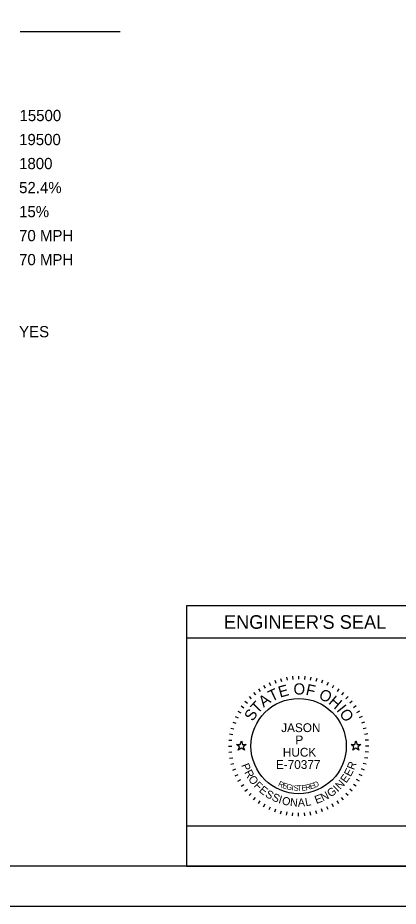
# Model space of a CAD drawing. Extents: x 39.8 to 73.8, y 13 to 35.
# Drawn here: x 47.48 to 52.23, y 12.96 to 24.06 of the extents above; entities that cross this region are included whole.
import ezdxf

# ---------------------------------------------------------------- set-up
doc = ezdxf.new("R2010")
doc.units = 0
for name, color, linetype in [('Default', 7, 'Continuous'), ('SH_Border', 7, 'Continuous'), ('SH_Cut_Line', 7, 'Continuous'), ('SH_Data', 7, 'Continuous'), ('SH_Text', 7, 'Continuous')]:
    doc.layers.add(name, color=color, linetype=linetype)

msp = doc.modelspace()

# ---------------------------------------------------------------- linework, layer by layer
at = {"layer": 'Default'}
for points in [[(50.214, 14.985), (50.26, 14.985), (50.275, 15.03), (50.289, 14.985), (50.336, 14.985), (50.298, 14.957), (50.313, 14.913), (50.275, 14.94), (50.237, 14.913), (50.251, 14.957)], [(51.644, 14.985), (51.69, 14.985), (51.705, 15.03), (51.719, 14.985), (51.766, 14.985), (51.728, 14.957), (51.743, 14.913), (51.705, 14.94), (51.667, 14.913), (51.681, 14.957)]]:
    msp.add_lwpolyline(points, close=True, dxfattribs=at)
at = {"layer": 'SH_Border'}
msp.add_lwpolyline([(41.263, 34.465), (73.263, 34.465), (73.263, 13.465), (41.263, 13.465)], close=True, dxfattribs=at)
at = {"layer": 'SH_Cut_Line'}
msp.add_lwpolyline([(39.763, 12.965), (73.763, 12.965), (73.763, 34.965), (39.763, 34.965)], close=True, dxfattribs=at)
at = {"layer": 'SH_Data'}
for p, q in [((48.763, 23.887), (47.513, 23.887)), ((52.39, 16.715), (49.59, 16.715)), ((49.59, 16.715), (49.59, 13.465)), ((52.39, 16.315), (49.59, 16.315)), ((50.62, 15.758), (50.637, 15.722)), ((50.691, 15.787), (50.704, 15.75)), ((50.763, 15.81), (50.774, 15.772)), ((50.838, 15.827), (50.845, 15.787)), ((50.914, 15.837), (50.917, 15.797)), ((50.99, 15.84), (50.99, 15.8)), ((51.066, 15.837), (51.063, 15.797)), ((51.142, 15.827), (51.135, 15.787)), ((51.216, 15.81), (51.206, 15.772)), ((51.289, 15.787), (51.275, 15.75)), ((51.36, 15.758), (51.343, 15.722)), ((50.488, 15.682), (50.511, 15.649)), ((50.552, 15.723), (50.572, 15.688)), ((51.427, 15.723), (51.407, 15.688)), ((51.492, 15.682), (51.469, 15.649)), ((50.371, 15.584), (50.399, 15.555)), ((50.427, 15.635), (50.453, 15.605)), ((51.552, 15.635), (51.527, 15.605)), ((51.609, 15.584), (51.58, 15.555)), ((50.273, 15.467), (50.306, 15.444)), ((50.32, 15.527), (50.35, 15.502)), ((51.66, 15.527), (51.63, 15.502)), ((51.707, 15.467), (51.674, 15.444)), ((50.197, 15.335), (50.233, 15.318)), ((50.232, 15.402), (50.267, 15.382)), ((51.748, 15.402), (51.713, 15.382)), ((51.783, 15.335), (51.747, 15.318)), ((50.168, 15.264), (50.205, 15.251)), ((51.812, 15.264), (51.775, 15.251)), ((50.128, 15.117), (50.168, 15.11)), ((50.145, 15.191), (50.183, 15.181)), ((51.835, 15.191), (51.796, 15.181)), ((51.852, 15.117), (51.812, 15.11)), ((50.118, 15.041), (50.158, 15.038)), ((51.862, 15.041), (51.822, 15.038)), ((50.115, 14.965), (50.155, 14.965)), ((50.118, 14.889), (50.158, 14.892)), ((51.862, 14.889), (51.822, 14.892)), ((51.865, 14.965), (51.825, 14.965)), ((50.128, 14.813), (50.168, 14.82)), ((51.852, 14.813), (51.812, 14.82)), ((50.145, 14.739), (50.183, 14.749)), ((50.168, 14.666), (50.205, 14.679)), ((51.812, 14.666), (51.775, 14.679)), ((51.835, 14.739), (51.796, 14.749)), ((50.197, 14.595), (50.233, 14.612)), ((50.232, 14.527), (50.267, 14.547)), ((51.748, 14.527), (51.713, 14.547)), ((51.783, 14.595), (51.747, 14.612)), ((50.273, 14.463), (50.306, 14.486)), ((50.32, 14.403), (50.35, 14.428)), ((51.66, 14.403), (51.63, 14.428)), ((51.707, 14.463), (51.674, 14.486)), ((50.371, 14.346), (50.399, 14.375)), ((50.427, 14.295), (50.453, 14.325)), ((51.552, 14.295), (51.527, 14.325)), ((51.609, 14.346), (51.58, 14.375)), ((50.488, 14.248), (50.511, 14.281)), ((50.552, 14.207), (50.572, 14.242)), ((50.62, 14.172), (50.637, 14.208)), ((51.36, 14.172), (51.343, 14.208)), ((51.427, 14.207), (51.407, 14.242)), ((51.492, 14.248), (51.469, 14.281)), ((50.691, 14.143), (50.704, 14.18)), ((50.763, 14.12), (50.774, 14.158)), ((50.838, 14.103), (50.845, 14.143)), ((50.914, 14.093), (50.917, 14.133)), ((50.99, 14.09), (50.99, 14.13)), ((51.066, 14.093), (51.063, 14.133)), ((51.142, 14.103), (51.135, 14.143)), ((51.216, 14.12), (51.206, 14.158)), ((51.289, 14.143), (51.275, 14.18)), ((52.39, 13.465), (49.59, 13.465))]:
    msp.add_line(p, q, dxfattribs=at)
msp.add_lwpolyline([(52.39, 13.465), (52.39, 13.965), (49.59, 13.965), (49.59, 13.465)], close=True, dxfattribs=at)
msp.add_circle((50.99, 14.965), 0.595, dxfattribs=at)

# ---------------------------------------------------------------- texts
for s, height, p in [("ENGINEER'S SEAL", 0.17, (50.057, 16.43)), ('JASON', 0.11, (50.772, 15.14)), ('P', 0.11, (50.95, 14.987)), ('HUCK', 0.11, (50.793, 14.833)), ('E-70377', 0.11, (50.706, 14.68))]:
    msp.add_text(s, height=height, dxfattribs=at).set_placement(p)
for s, height, rotation, p in [('T', 0.14, 25.7167, (50.652, 15.517)), ('E', 0.14, 15.7571, (50.758, 15.569)), ('O', 0.14, 359.7812, (50.925, 15.609)), ('F', 0.14, 347.4362, (51.071, 15.607)), ('O', 0.14, 332.2586, (51.23, 15.566)), ('T', 0.14, 46.4344, (50.478, 15.361)), ('A', 0.14, 36.4747, (50.553, 15.443)), ('H', 0.14, 319.9136, (51.353, 15.501)), ('S', 0.14, 57.1924, (50.418, 15.266)), ('I', 0.14, 308.367, (51.456, 15.413)), ('O', 0.14, 303.1491, (51.492, 15.374)), ('R', 0.1, 69.2322, (51.682, 14.66)), ('P', 0.1, 291.494, (50.272, 14.727)), ('R', 0.1, 298.7311, (50.309, 14.637)), ('E', 0.1, 61.9951, (51.638, 14.575)), ('O', 0.1, 306.4666, (50.355, 14.553)), ('N', 0.1, 47.0224, (51.51, 14.416)), ('E', 0.1, 54.758, (51.583, 14.496)), ('F', 0.1, 314.7068, (50.424, 14.463)), ('E', 0.1, 321.4393, (50.488, 14.4)), ('R', 0.07, 334.487, (50.727, 14.47)), ('E', 0.07, 341.04, (50.781, 14.445)), ('G', 0.07, 347.4752, (50.831, 14.427)), ('I', 0.07, 353.7858, (50.899, 14.412)), ('S', 0.07, 356.8926, (50.926, 14.408)), ('T', 0.07, 3.0061, (50.976, 14.404)), ('E', 0.07, 6.0117, (51.029, 14.406)), ('R', 0.07, 11.9184, (51.082, 14.412)), ('E', 0.07, 17.6836, (51.14, 14.425)), ('D', 0.07, 23.3052, (51.191, 14.442)), ('G', 0.1, 35.0469, (51.388, 14.322)), ('I', 0.1, 43.287, (51.477, 14.386)), ('S', 0.1, 328.6764, (50.564, 14.34)), ('S', 0.1, 335.9134, (50.646, 14.292)), ('I', 0.1, 343.1505, (50.731, 14.255)), ('O', 0.1, 346.8859, (50.774, 14.24)), ('N', 0.1, 355.1261, (50.879, 14.217)), ('L', 0.1, 10.0987, (51.079, 14.214)), ('E', 0.1, 20.0742, (51.211, 14.242)), ('N', 0.1, 27.3113, (51.294, 14.272)), ('A', 0.1, 2.8617, (50.982, 14.209))]:
    msp.add_text(s, height=height, rotation=rotation, dxfattribs=at).set_placement(p)
at = {"layer": 'SH_Text'}
for s, p in [('15500', (47.505, 22.771)), ('19500', (47.5, 22.471)), ('1800', (47.5, 22.171)), ('52.4%', (47.5, 21.871)), ('15%', (47.5, 21.571)), ('70 MPH', (47.5, 21.271)), ('70 MPH', (47.5, 20.971)), ('YES', (47.5, 20.071))]:
    msp.add_text(s, height=0.14, dxfattribs=at).set_placement(p)

doc.saveas('drawing.dxf')
